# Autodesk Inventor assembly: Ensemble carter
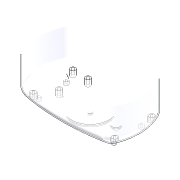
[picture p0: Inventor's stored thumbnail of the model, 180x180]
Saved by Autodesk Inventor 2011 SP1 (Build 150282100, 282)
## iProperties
Created: 2010-12
Part Number: Ensemble carter
Document SubType Name: Assembly
Designer: eric
Author: eric
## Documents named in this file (2)
- D:\eduinventor\maquettesaip2011\machineàpain\Workspace\Ensemble carter.iam
- D:\eduinventor\maquettesaip2011\machineàpain\Workspace\carter inferieur.ipt
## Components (1 placed, 1 different names)
1. carter inferieur:1
